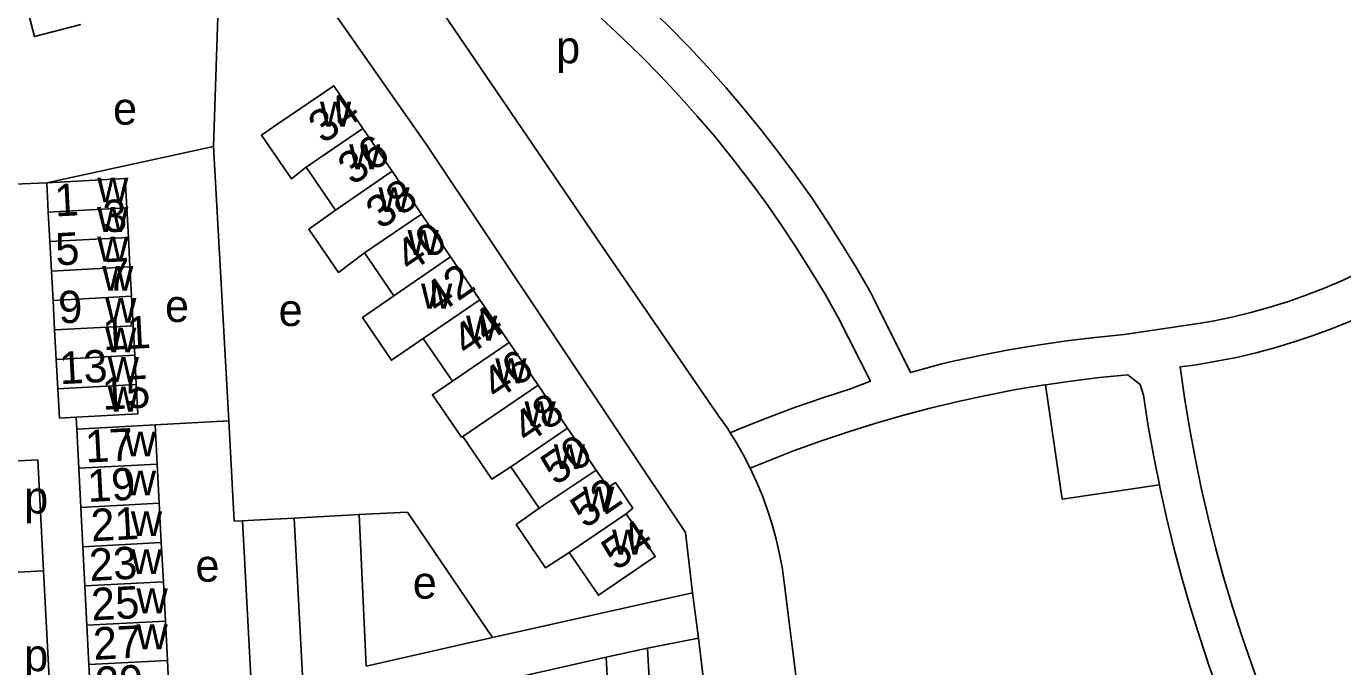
# Model space of a CAD drawing. Extents: x 157569 to 159501, y 382907 to 384670.
# Drawn here: x 158892.8 to 159055.8, y 383558 to 383637.3 of the extents above; entities that cross this region are included whole.
import ezdxf

# ---------------------------------------------------------------- set-up
doc = ezdxf.new("R2010")
doc.units = 0
for name, color, linetype in [('BLT_Basislijn', 7, 'Continuous'), ('BLT_Bebouwing', 7, 'Continuous'), ('BLT_Centroide', 7, 'Continuous'), ('BLT_Huisnummer', 7, 'Continuous'), ('BLT_Huisnummer_ tussenligend', 7, 'Continuous'), ('BLT_Onderverdeling_panden', 7, 'Continuous'), ('BLT_Straatnaam', 7, 'Continuous')]:
    doc.layers.add(name, color=color, linetype=linetype)

msp = doc.modelspace()

# ---------------------------------------------------------------- linework, layer by layer
at = {"layer": 'BLT_Basislijn'}
for p, q in [((158916, 383622.36), (158916.64, 383641.89)), ((158895.33, 383617.87), (158916, 383622.36)), ((158916, 383622.36), (158917.86, 383588.41)), ((158895.33, 383617.87), (158890.33, 383617.66)), ((159028.74, 383599.1), (159037.93, 383600.45)), ((158899.05, 383587.37), (158898.97, 383588.84)), ((158908.76, 383587.91), (158917.86, 383588.41)), ((158917.86, 383588.41), (158918.54, 383575.97)), ((158889.53, 383583.33), (158894.24, 383583.58)), ((158894.24, 383583.58), (158894.95, 383569.81)), ((158934.03, 383576.79), (158925.95, 383576.36)), ((158934.87, 383558.03), (158934.03, 383576.79)), ((158919.59, 383576.02), (158918.54, 383575.97)), ((158894.95, 383569.81), (158890.25, 383569.6)), ((158894.95, 383569.81), (158895.63, 383556.56)), ((158950.53, 383561.59), (158975.3, 383567.11)), ((158976.02, 383561.51), (158975.3, 383567.11)), ((158986.65, 383568.38), (158992.35, 383522.47)), ((158950.53, 383561.59), (158934.87, 383558.03)), ((158976.02, 383561.51), (158969.71, 383560.27)), ((158991.4, 383436.09), (158976.02, 383561.51)), ((158935.24, 383552.52), (158964.58, 383559.14)), ((158964.58, 383559.14), (158969.71, 383560.27))]:
    msp.add_line(p, q, dxfattribs=at)
for points in [[(158934.07, 383654.17), (158963.94, 383610.24), (158978.52, 383589.03)], [(158914.57, 383649.86), (158921.71, 383652.1), (158942.31, 383622.66), (158974.41, 383574.58), (158975.3, 383567.11)], [(158967.34, 383641.97), (158969.87, 383639.62), (158972.35, 383637.21), (158974.77, 383634.74), (158977.13, 383632.22), (158979.44, 383629.64), (158981.68, 383627.01), (158983.87, 383624.33), (158985.99, 383621.6), (158988.05, 383618.82), (158990.04, 383616), (158991.97, 383613.13), (158993.83, 383610.21), (158995.62, 383607.26), (158997.34, 383604.26), (158997.71, 383603.6)], [(158963.98, 383638.27), (158966.47, 383635.95), (158968.9, 383633.58), (158971.28, 383631.15), (158973.6, 383628.67), (158975.86, 383626.13), (158978.07, 383623.55), (158980.21, 383620.91), (158982.28, 383618.22), (158984.3, 383615.48), (158986.24, 383612.69), (158988.13, 383609.86), (158989.94, 383606.99), (158991.69, 383604.07), (158993.33, 383601.18)], [(159084.18, 383628.08), (159082.67, 383626.18), (159081.09, 383624.34), (159079.45, 383622.54), (159077.76, 383620.81), (159076.01, 383619.13), (159074.2, 383617.51), (159072.34, 383615.95), (159070.43, 383614.45), (159068.48, 383613.01), (159066.47, 383611.64), (159064.43, 383610.34), (159062.34, 383609.1), (159060.21, 383607.94), (159058.04, 383606.84), (159055.84, 383605.82), (159053.61, 383604.87), (159051.35, 383603.99), (159049.06, 383603.19), (159046.74, 383602.47), (159044.4, 383601.82), (159042.04, 383601.25), (159039.67, 383600.76), (159037.93, 383600.45)], [(158997.71, 383603.6), (159002.26, 383594.4), (159006.15, 383595.46)], [(158993.33, 383601.18), (158997.31, 383593.3), (158994.86, 383592.38)], [(159056.93, 383600.84), (159054.61, 383599.89), (159052.26, 383599.01), (159049.89, 383598.21), (159047.49, 383597.48), (159045.07, 383596.83), (159042.62, 383596.26), (159040.17, 383595.77), (159037.69, 383595.35), (159035.67, 383595.07)], [(159028.74, 383599.1), (159025.15, 383598.73), (159021.57, 383598.29), (159018.01, 383597.77), (159014.45, 383597.18), (159010.91, 383596.5), (159007.38, 383595.74), (159006.15, 383595.46)], [(159035.67, 383595.07), (159036.2, 383591.31), (159036.81, 383587.55), (159037.5, 383583.82), (159038.27, 383580.09), (159039.12, 383576.39), (159040.04, 383572.7), (159041.04, 383569.03), (159042.12, 383565.39), (159043.28, 383561.76), (159044.51, 383558.17), (159045.81, 383554.6), (159047.2, 383551.05), (159048.65, 383547.54), (159050.18, 383544.06), (159053.97, 383536.19)], [(159029.19, 383594.11), (159025.65, 383593.76), (159022.13, 383593.32), (159018.99, 383592.86)], [(159031.11, 383591.56), (159030.69, 383592.89), (159029.19, 383594.11)], [(158994.86, 383592.38), (158991.43, 383591.27), (158988.02, 383590.09), (158984.65, 383588.82), (158981.3, 383587.49), (158979.95, 383586.92)], [(159018.99, 383592.86), (159018.62, 383592.81), (159015.12, 383592.22), (159011.63, 383591.54), (159008.16, 383590.79), (159004.71, 383589.96), (159001.28, 383589.06), (158997.87, 383588.07), (158994.48, 383587.01), (158991.12, 383585.88), (158987.78, 383584.67), (158984.47, 383583.38), (158982.43, 383582.54)], [(159018.99, 383592.86), (159021.05, 383578.71), (159033.08, 383580.46)], [(159031.11, 383591.56), (159031.7, 383587.76), (159032.38, 383583.96), (159033.08, 383580.46)], [(158978.52, 383589.03), (158979.6, 383587.48), (158979.95, 383586.92)], [(158979.95, 383586.92), (158980.61, 383585.89), (158981.54, 383584.25), (158982.43, 383582.54)], [(158982.43, 383582.54), (158983.21, 383580.86), (158983.93, 383579.12), (158984.58, 383577.35), (158985.15, 383575.56), (158985.65, 383573.74), (158986.07, 383571.9), (158986.41, 383570.04), (158986.65, 383568.38)], [(159033.08, 383580.46), (159033.14, 383580.18), (159033.97, 383576.42), (159034.88, 383572.68), (159035.87, 383568.95), (159036.94, 383565.25), (159038.08, 383561.57), (159039.3, 383557.91), (159040.6, 383554.28), (159041.97, 383550.68), (159043.41, 383547.11), (159044.93, 383543.56), (159046.52, 383540.05), (159048.18, 383536.58), (159049.52, 383533.92)], [(158950.53, 383561.59), (158939.99, 383577.09), (158934.03, 383576.79)], [(158964.58, 383559.14), (158971.38, 383433.97), (158967.47, 383433.71)], [(158991.4, 383436.09), (158976.81, 383435.46), (158976.6, 383435.94), (158969.71, 383560.27)]]:
    msp.add_lwpolyline(points, dxfattribs=at)
at = {"layer": 'BLT_Bebouwing'}
for p, q in [((158934.48, 383624.6), (158938.1, 383619.3)), ((158931.07, 383614.5), (158927.45, 383619.8)), ((158938.1, 383619.3), (158941.71, 383614)), ((158895.33, 383617.87), (158905.05, 383618.41)), ((158895.52, 383614.24), (158895.33, 383617.87)), ((158905.05, 383618.41), (158905.24, 383614.76)), ((158895.52, 383614.24), (158895.72, 383610.59)), ((158905.44, 383611.12), (158905.24, 383614.76)), ((158941.71, 383614), (158945.33, 383608.7)), ((158905.44, 383611.12), (158905.63, 383607.47)), ((158895.72, 383610.59), (158895.92, 383606.95)), ((158938.31, 383603.9), (158934.69, 383609.2)), ((158945.33, 383608.7), (158948.95, 383603.4)), ((158895.92, 383606.95), (158896.11, 383603.3)), ((158905.83, 383603.83), (158905.63, 383607.47)), ((158896.11, 383603.3), (158896.31, 383599.66)), ((158905.83, 383603.83), (158906.03, 383600.18)), ((158948.95, 383603.4), (158952.57, 383598.1)), ((158896.31, 383599.66), (158896.51, 383596.01)), ((158906.22, 383596.54), (158906.03, 383600.18)), ((158945.55, 383593.3), (158941.93, 383598.6)), ((158952.57, 383598.1), (158956.19, 383592.8)), ((158906.22, 383596.54), (158906.42, 383592.89)), ((158896.51, 383596.01), (158896.7, 383592.37)), ((158906.61, 383589.25), (158906.42, 383592.89)), ((158896.7, 383592.37), (158896.9, 383588.73)), ((158956.19, 383592.8), (158959.81, 383587.5)), ((158896.9, 383588.73), (158898.97, 383588.84)), ((158898.97, 383588.84), (158906.61, 383589.25)), ((158899.05, 383587.37), (158908.76, 383587.91)), ((158899.3, 383582.55), (158899.05, 383587.37)), ((158908.76, 383587.91), (158909.02, 383583.05)), ((158959.81, 383587.5), (158963.37, 383582.28)), ((158899.3, 383582.55), (158899.55, 383577.68)), ((158909.02, 383583.05), (158909.27, 383578.19)), ((158956.29, 383577.57), (158952.78, 383582.7)), ((158899.8, 383572.82), (158899.55, 383577.68)), ((158909.27, 383578.19), (158909.52, 383573.32)), ((158920.74, 383554.41), (158919.59, 383576.02)), ((158899.8, 383572.82), (158900.05, 383567.96)), ((158909.52, 383573.32), (158909.77, 383568.46)), ((158909.77, 383568.46), (158910.02, 383563.59)), ((158900.3, 383563.09), (158900.05, 383567.96)), ((158910.02, 383563.59), (158910.27, 383558.73)), ((158900.3, 383563.09), (158900.56, 383558.23)), ((158910.27, 383558.73), (158910.52, 383553.87)), ((158900.81, 383553.34), (158900.56, 383558.23))]:
    msp.add_line(p, q, dxfattribs=at)
for points in [[(158899.54, 383637.46), (158893.83, 383635.98), (158891.77, 383643.94)], [(158927.45, 383619.8), (158925.62, 383618.37), (158921.92, 383623.79), (158923.83, 383625.1), (158926.73, 383627.08), (158930.86, 383629.9), (158934.48, 383624.6)], [(158934.69, 383609.2), (158931.44, 383606.78), (158927.79, 383612.12), (158931.07, 383614.5)], [(158941.93, 383598.6), (158938.01, 383595.9), (158934.41, 383601.18), (158938.31, 383603.9)], [(158946.83, 383586.45), (158946.69, 383586.36), (158943.08, 383591.63), (158945.55, 383593.3)], [(158952.78, 383582.7), (158950.43, 383581.18), (158946.83, 383586.45)], [(158963.37, 383582.28), (158964.84, 383580.13), (158965.74, 383580.75), (158967.9, 383577.59), (158967.05, 383576.89)], [(158960.02, 383572.1), (158957.1, 383570.18), (158953.43, 383575.55), (158956.29, 383577.57)], [(158967.05, 383576.89), (158970.67, 383571.59), (158963.64, 383566.8), (158960.82, 383570.92), (158960.02, 383572.1)], [(158919.59, 383576.02), (158920.96, 383576.1), (158925.95, 383576.36)], [(158934.67, 383410.51), (158930.01, 383500), (158925.95, 383576.36)]]:
    msp.add_lwpolyline(points, dxfattribs=at)
at = {"layer": 'BLT_Onderverdeling_panden'}
for p, q in [((158934.48, 383624.6), (158927.45, 383619.8)), ((158938.1, 383619.3), (158931.07, 383614.5)), ((158905.24, 383614.76), (158895.52, 383614.24)), ((158941.71, 383614), (158934.69, 383609.2)), ((158895.72, 383610.59), (158905.44, 383611.12)), ((158945.33, 383608.7), (158938.31, 383603.9)), ((158905.63, 383607.47), (158895.92, 383606.95)), ((158896.11, 383603.3), (158905.83, 383603.83)), ((158948.95, 383603.4), (158941.93, 383598.6)), ((158906.03, 383600.18), (158896.31, 383599.66)), ((158952.57, 383598.1), (158945.55, 383593.3)), ((158896.51, 383596.01), (158906.22, 383596.54)), ((158906.42, 383592.89), (158896.7, 383592.37)), ((158956.19, 383592.8), (158946.83, 383586.45)), ((158959.81, 383587.5), (158952.78, 383582.7)), ((158909.02, 383583.05), (158899.3, 383582.55)), ((158963.37, 383582.28), (158956.29, 383577.57)), ((158899.55, 383577.68), (158909.27, 383578.19)), ((158967.05, 383576.89), (158960.02, 383572.1)), ((158909.52, 383573.32), (158899.8, 383572.82)), ((158900.05, 383567.96), (158909.77, 383568.46)), ((158910.02, 383563.59), (158900.3, 383563.09)), ((158900.56, 383558.23), (158910.27, 383558.73))]:
    msp.add_line(p, q, dxfattribs=at)

# ---------------------------------------------------------------- texts
at = {"layer": 'BLT_Centroide'}
for s, p in [('p', (158958.4, 383632.68)), ('e', (158903.54, 383625.08)), ('w', (158929.16, 383624.84)), ('w', (158932.77, 383619.56)), ('w', (158901.58, 383615.46)), ('w', (158936.39, 383614.25)), ('w', (158901.58, 383611.8)), ('w', (158901.58, 383608.13)), ('w', (158940.01, 383608.94)), ('w', (158902.19, 383604.51)), ('w', (158941.68, 383602.31)), ('w', (158902.57, 383600.55)), ('e', (158909.98, 383600.65)), ('e', (158924.04, 383600.14)), ('w', (158947.25, 383598.34)), ('w', (158902.57, 383596.88)), ('w', (158902.89, 383593.22)), ('w', (158950.87, 383593.06)), ('w', (158902.89, 383589.55)), ('w', (158954.49, 383587.75)), ('w', (158905, 383583.99)), ('w', (158958.11, 383582.44)), ('w', (158905, 383579.18)), ('p', (158892.54, 383576.93)), ('w', (158961.73, 383577.16)), ('w', (158905.75, 383574.13)), ('w', (158965.34, 383571.84)), ('w', (158905.75, 383569.43)), ('e', (158913.75, 383568.49)), ('e', (158940.65, 383566.39)), ('w', (158906.45, 383564.58)), ('w', (158906.45, 383560.12)), ('p', (158892.54, 383557.4))]:
    msp.add_text(s, height=4, dxfattribs=at).set_placement(p)
at = {"layer": 'BLT_Huisnummer'}
for s, rotation, p in [('34', 34.3251, (158929.53, 383622.61)), ('1', 3.0105, (158896.4, 383613.7)), ('38', 34.3251, (158936.65, 383612)), ('5', 3.0105, (158896.5, 383607.64)), ('42', 34.3251, (158943.76, 383601.46)), ('9', 3.0105, (158896.87, 383600.44)), ('13', 3.0105, (158897, 383592.93)), ('46', 34.3251, (158951, 383590.84)), ('17', 3.0105, (158900.19, 383583.22)), ('50', 34.3251, (158958.3, 383580.3)), ('21', 3.0105, (158900.88, 383573.47)), ('54', 34.3251, (158965.81, 383569.75)), ('25', 3.0105, (158900.94, 383563.68)), ('29', 3.0105, (158901.45, 383553.92))]:
    msp.add_text(s, height=4, rotation=rotation, dxfattribs=at).set_placement(p)
at = {"layer": 'BLT_Huisnummer_ tussenligend'}
for s, rotation, p in [('36', 34.3251, (158933.18, 383617.47)), ('3', 3.0105, (158902.38, 383611.72)), ('40', 34.3251, (158940.29, 383606.66)), ('7', 3.0105, (158902.75, 383604.46)), ('11', 3.0105, (158902.35, 383597.13)), ('44', 34.3251, (158947.33, 383596.24)), ('15', 3.0105, (158902.29, 383589.76)), ('48', 34.3251, (158954.78, 383585.44)), ('19', 3.0105, (158900.45, 383578.34)), ('52', 34.3251, (158961.96, 383574.97)), ('23', 3.0105, (158900.68, 383568.56)), ('27', 3.0105, (158901.18, 383558.8))]:
    msp.add_text(s, height=4, rotation=rotation, dxfattribs=at).set_placement(p)
at = {"layer": 'BLT_Straatnaam'}
msp.add_text('CORNELIS VAN BIJNKERSHOEKSTRAAT', height=4.9999, rotation=14.6494, dxfattribs=at).set_placement((158775.77, 383617.75))

doc.saveas('drawing.dxf')
